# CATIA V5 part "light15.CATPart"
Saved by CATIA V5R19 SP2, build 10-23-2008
Part number: light15
Bounding box of the stored display mesh (mm): x 1461.862 to 1826.589, y -622.204 to 622.204, z 334.842 to 540.221
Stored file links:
  C:\BEHROOZ\catia learning\tarh haye mashin\hb\light15.CATPart
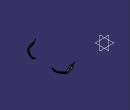
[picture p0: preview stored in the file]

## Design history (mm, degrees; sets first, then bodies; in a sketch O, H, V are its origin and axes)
Body1 (main body)
  DatumSurface1
  ThickSurface1: Surface DatumSurface1, TopOffset 15, BotOffset -5
  DatumSurface2
  Plane1: stored without definition
  ThickSurface2: Surface DatumSurface2, TopOffset 15, BotOffset -5
  Sketch1 on Plane1, origin (1983, 0, 0), H (0, 1, 0), V (0, 0, 1)
    spline S1 through (586.371, 508.498) (579.8971, 496.0501) (578.8527, 472.4985) (590.0191, 448.1779) (598.0694, 429.7711) (588.8305, 396.7529) (562.4122, 379.974) (529.2045, 368.3393) (458.9071, 354.8117) (395.1128, 350.167) (366.8445, 349.7468) (337.1108, 350.9854) (314.0708, 358.2742) (293.3869, 370.2473) (278.058, 381.5571) (263.1428, 389.8645)
    line L1 (586.371, 508.498) -> (611.5471, 546.1805)
    point P2 (586.371, 508.498)
    arc A1 centre (228.0472, 278.5137) radius 116.7506 from (211.532, 394.0903) to (263.1428, 389.8645) cw
    point P3 (263.1428, 389.8645)
    spline S2 through (-586.371, 508.498) (-579.8971, 496.0501) (-578.8527, 472.4985) (-590.0191, 448.1779) (-598.0694, 429.7711) (-588.8305, 396.7529) (-562.4122, 379.974) (-529.2045, 368.3393) (-458.9071, 354.8117) (-395.1128, 350.167) (-366.8445, 349.7468) (-337.1108, 350.9854) (-314.0708, 358.2742) (-293.3869, 370.2473) (-278.058, 381.5571) (-263.1428, 389.8645)
    line L2 (-586.371, 508.498) -> (-608.3117, 541.3379)
    arc A2 centre (-228.0472, 278.5137) radius 116.7506 from (-211.532, 394.0903) to (-263.1428, 389.8645) ccw
    point P11 (586.371, 508.498)
    point P12 (263.1428, 389.8645)
    coincidence: P11 P2, P12 P3
  Pocket1: profile Sketch1, direction (-1, 0, 0), length 20, opposite side length -577, thin wall 6, second thickness 7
